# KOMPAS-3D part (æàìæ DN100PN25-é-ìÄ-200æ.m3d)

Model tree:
1. Объединить компоненты:1  (labels: СЕНС DN100PN25-В-НО-200С)

Referenced files in D:\Савин\!СЕНСОР\3D для заказчика\!Новый перечень\СЕНС\7. СЕНС-В-НО-200С\DN100\: СЕНС DN100PN25-В-НО-200С.a3d
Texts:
  СЕНС DN100PN25-В-НО-200С
  ООО НПП Сенсор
